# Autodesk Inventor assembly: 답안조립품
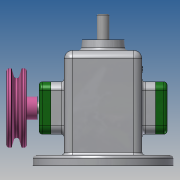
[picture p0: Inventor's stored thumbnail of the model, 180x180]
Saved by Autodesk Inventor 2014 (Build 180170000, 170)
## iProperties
Created: 2021-08
Part Number: 답안조립품
Document SubType Name: Assembly
Designer: kb542
Author: kb542
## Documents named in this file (16)
- C:\Users\kb542\Desktop\710806V1009\답안조립품.iam
- C:\Users\kb542\Desktop\710806V1009\본체.ipt
- C:\Users\kb542\Desktop\710806V1009\뒤커버.ipt
- C:\Users\kb542\Desktop\710806V1009\앞커버.ipt
- C:\Users\kb542\Desktop\710806V1009\오일 실 12 25 7.ipt
- C:\Users\kb542\Desktop\710806V1009\편심축.ipt
- C:\Users\kb542\Desktop\710806V1009\베어링 12x32x10.ipt
- C:\Users\kb542\Desktop\710806V1009\링크.ipt
- C:\Users\kb542\Desktop\710806V1009\키 4x4x10.ipt
- C:\Users\kb542\Desktop\710806V1009\V벨트풀리.ipt
- C:\Users\kb542\Desktop\710806V1009\슬라이드.ipt
- C:\Users\kb542\Desktop\710806V1009\고정핀 1.2x8.ipt
- C:\Users\kb542\Desktop\710806V1009\핀 5x18.ipt
- C:\Users\kb542\Desktop\710806V1009\멈춤나사 M3x8.ipt
- C:\Users\kb542\Desktop\710806V1009\부시.ipt
- C:\Users\kb542\Desktop\710806V1009\볼트 M4.ipt
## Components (3 placed, 3 different names)
1. V벨트풀리:1 — 플러쉬:2
2. 고정핀 1.2x8:1
3. 핀 5x18:1
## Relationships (1: Flush 1)
- 플러쉬:2 [Flush]: V벨트풀리:1
